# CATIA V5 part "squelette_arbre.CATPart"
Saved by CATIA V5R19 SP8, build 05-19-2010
Part number: squelette_arbre
Publications: "Plan.1"
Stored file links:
  G:\EU_thinkMotion\CFAO_2010\MMS_groupe3\MMS_groupe3\A reprendre\amenand\amenand\squelette_arbre.CATPart
  F:\thinkmotion CFAO v12.1\essuie_glace.CATProduct
  G:\EU_thinkMotion\CFAO_2010\MMS_groupe3\MMS_groupe3\A reprendre\amenand\amenand\balancier.CATPart
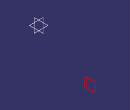
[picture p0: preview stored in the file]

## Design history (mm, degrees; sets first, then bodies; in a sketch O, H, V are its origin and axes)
Set1
  Plane1: linked copy from another document
Set2 "set géométrique.13"
  Plane2: type Offset, RefPlane Plane1, Offset 5
Body1 (main body)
